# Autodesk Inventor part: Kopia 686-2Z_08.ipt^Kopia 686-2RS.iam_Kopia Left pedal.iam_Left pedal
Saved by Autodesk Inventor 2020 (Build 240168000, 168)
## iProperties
Created: 2017-10
Part Number: Kopia 686-2Z_08.ipt^Kopia 686-2RS.iam_Kopia Left pedal.iam_Left pedal
Material: Ogólny
Document SubType Name: Modeling
Designer: Tomasz
Density: 1 g/cm^3
Appearance: Domyślna
Sending System: SolidWorks 2017
Last Author: Tomasz
Last Saved: 2017-10-01
Author: Tomasz
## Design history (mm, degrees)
